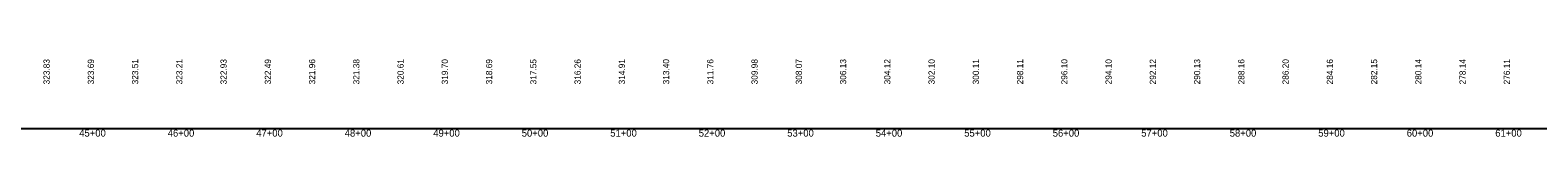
# Model space of a CAD drawing. Extents: x 1838386 to 1955906, y 719739 to 834437.
# Drawn here: x 1881790 to 1883494, y 825624 to 825711 of the extents above; entities that cross this region are included whole.
import ezdxf

# ---------------------------------------------------------------- set-up
doc = ezdxf.new("R2010")
doc.units = 0
for name, color, linetype in [('RD_DDB_StaTX', 7, 'Continuous'), ('RD_DDB_StripGrade', 7, 'Continuous'), ('RD_GPK_Profile_Cell', 7, 'Continuous')]:
    doc.layers.add(name, color=color, linetype=linetype)

msp = doc.modelspace()

# ---------------------------------------------------------------- linework, layer by layer
at = {"layer": 'RD_GPK_Profile_Cell'}
msp.add_line((1878363.1, 825633.1), (1904963.1, 825633.1), dxfattribs=at)

# ---------------------------------------------------------------- texts
at = {"layer": 'RD_DDB_StaTX'}
for s, p in [('45+00', (1881845.5, 825624.1)), ('46+00', (1881945.5, 825624.1)), ('47+00', (1882045.5, 825624.1)), ('48+00', (1882145.5, 825624.1)), ('49+00', (1882245.5, 825624.1)), ('50+00', (1882345.5, 825624.1)), ('51+00', (1882445.5, 825624.1)), ('52+00', (1882545.5, 825624.1)), ('53+00', (1882645.5, 825624.1)), ('54+00', (1882745.5, 825624.1)), ('55+00', (1882845.5, 825624.1)), ('56+00', (1882945.5, 825624.1)), ('57+00', (1883045.5, 825624.1)), ('58+00', (1883145.5, 825624.1)), ('59+00', (1883245.5, 825624.1)), ('60+00', (1883345.5, 825624.1)), ('61+00', (1883445.5, 825624.1))]:
    msp.add_text(s, height=8, dxfattribs=at).set_placement(p)
at = {"layer": 'RD_DDB_StripGrade'}
for s, p in [('323.83', (1881812.1, 825683.1)), ('323.69', (1881862.1, 825683.1)), ('323.51', (1881912.1, 825683.1)), ('323.21', (1881962.1, 825683.1)), ('322.93', (1882012.1, 825683.1)), ('322.49', (1882062.1, 825683.1)), ('321.96', (1882112.1, 825683.1)), ('321.38', (1882162.1, 825683.1)), ('320.61', (1882212.1, 825683.1)), ('319.70', (1882262.1, 825683.1)), ('318.69', (1882312.1, 825683.1)), ('317.55', (1882362.1, 825683.1)), ('316.26', (1882412.1, 825683.1)), ('314.91', (1882462.1, 825683.1)), ('313.40', (1882512.1, 825683.1)), ('311.76', (1882562.1, 825683.1)), ('309.98', (1882612.1, 825683.1)), ('308.07', (1882662.1, 825683.1)), ('306.13', (1882712.1, 825683.1)), ('304.12', (1882762.1, 825683.1)), ('302.10', (1882812.1, 825683.1)), ('300.11', (1882862.1, 825683.1)), ('298.11', (1882912.1, 825683.1)), ('296.10', (1882962.1, 825683.1)), ('294.10', (1883012.1, 825683.1)), ('292.12', (1883062.1, 825683.1)), ('290.13', (1883112.1, 825683.1)), ('288.16', (1883162.1, 825683.1)), ('286.20', (1883212.1, 825683.1)), ('284.16', (1883262.1, 825683.1)), ('282.15', (1883312.1, 825683.1)), ('280.14', (1883362.1, 825683.1)), ('278.14', (1883412.1, 825683.1)), ('276.11', (1883462.1, 825683.1))]:
    msp.add_text(s, height=7, rotation=90, dxfattribs=at).set_placement(p)

doc.saveas('drawing.dxf')
